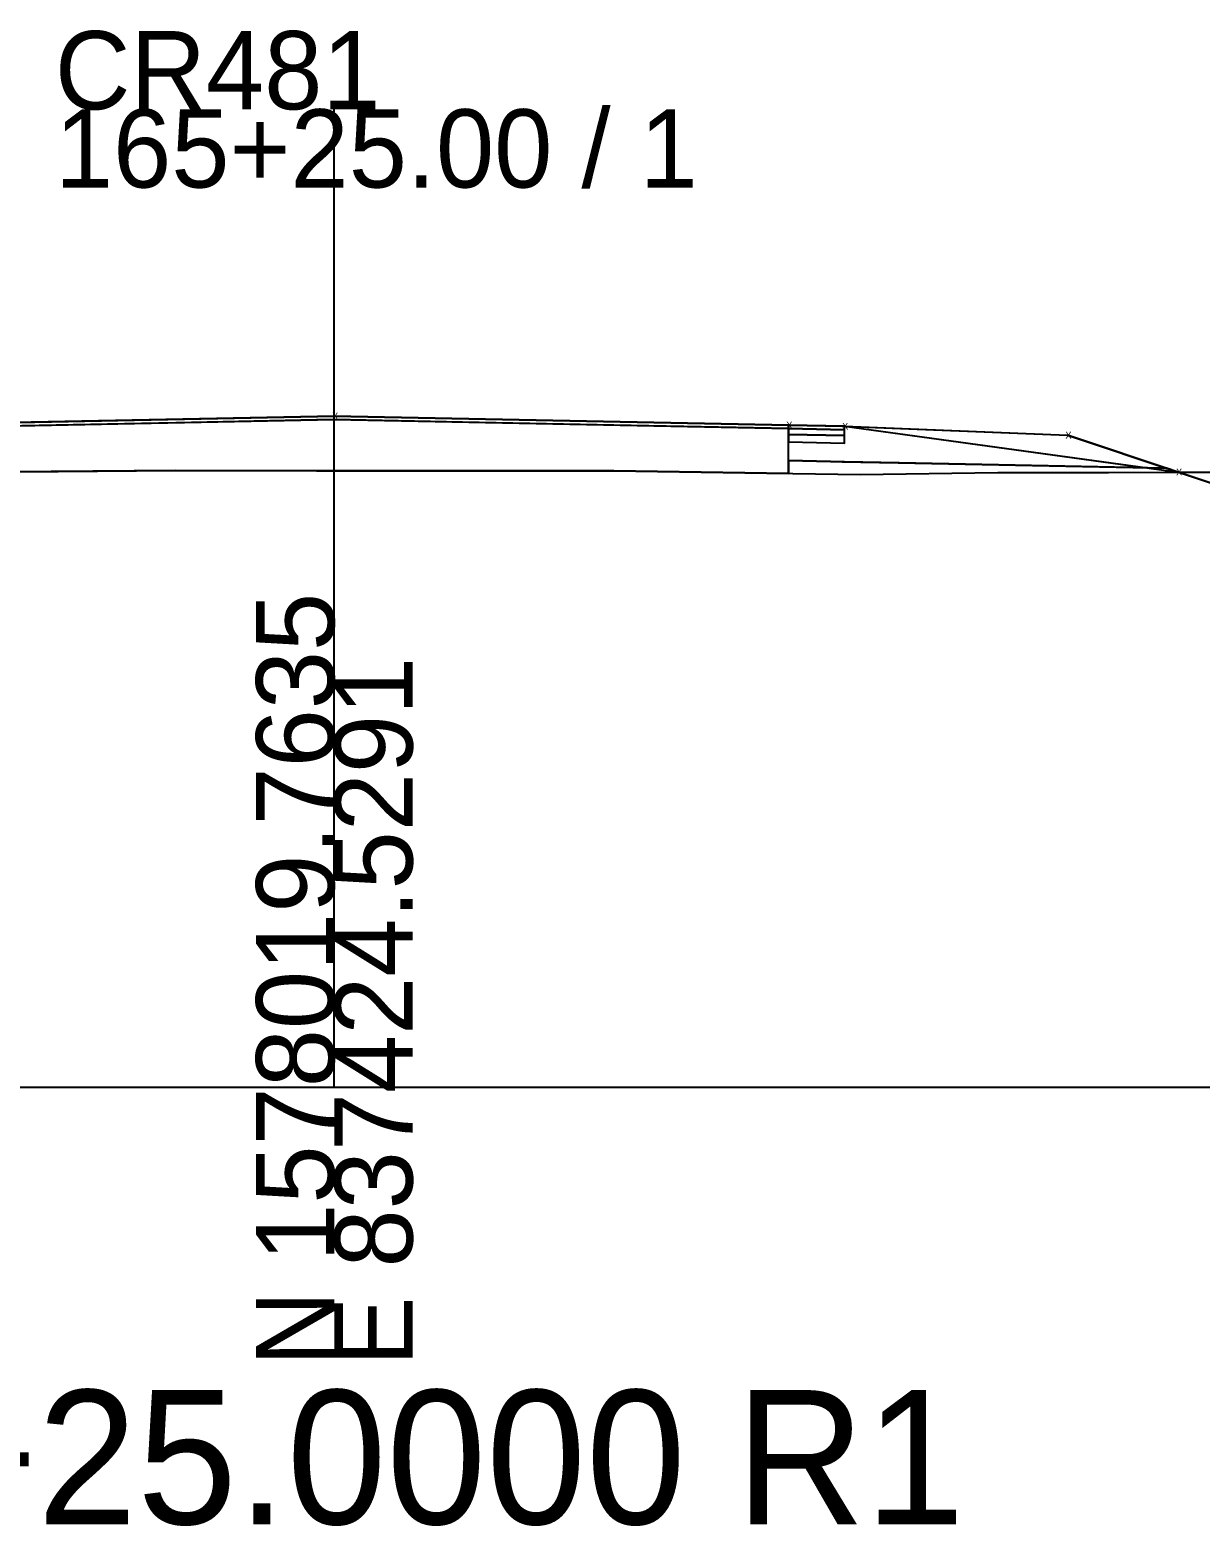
# Model space of a CAD drawing. Extents: x -26 to 303, y -16 to 6048.
# Drawn here: x 139.1 to 181, y 3984.3 to 4037.8 of the extents above; entities that cross this region are included whole.
import ezdxf

# ---------------------------------------------------------------- set-up
doc = ezdxf.new("R2010")
doc.units = 0
for name, color, linetype in [('ASPHALT_19MM1', 7, 'Continuous'), ('ASPHALT_9_5MM1', 7, 'Continuous'), ('CONST_LV3', 7, 'Continuous'), ('Draft_XS_Text', 7, 'Continuous'), ('DTM_P_FINISHED_GRADE2', 7, 'Continuous'), ('DTM_TEMP_DROP', 7, 'Continuous'), ('DTM_X_GROUND', 7, 'Continuous'), ('TRANS_PAVED_SHOULDERS', 7, 'Continuous'), ('X_PROFILES_1', 7, 'Continuous'), ('XS_CELL', 7, 'Continuous'), ('XS_M_SHAPES_EARTHWORK', 7, 'Continuous'), ('XS_P_ASPHALT', 7, 'Continuous'), ('XS_P_GROUND', 7, 'Continuous'), ('XS_P_NULL_POINT', 7, 'Continuous'), ('XS_P_SHOULDER', 7, 'Continuous'), ('XS_P_SUBGRADE_GRANULAR', 7, 'Continuous'), ('XS_P_SUBGRADE_LEVELING', 7, 'Continuous'), ('XS_P_SUBGRADE_MILLING', 7, 'Continuous')]:
    doc.layers.add(name, color=color, linetype=linetype)

msp = doc.modelspace()

# ---------------------------------------------------------------- linework, layer by layer
at = {"layer": 'ASPHALT_19MM1'}
msp.add_lwpolyline([(166.254, 4023.361), (166.254, 4023.091), (168.254, 4023.051), (168.254, 4023.321), (166.254, 4023.361)], dxfattribs=at)
at = {"layer": 'ASPHALT_9_5MM1'}
msp.add_lwpolyline([(166.254, 4023.695), (166.254, 4023.57), (168.254, 4023.53), (168.254, 4023.655), (166.254, 4023.695)], dxfattribs=at)
at = {"layer": 'CONST_LV3'}
for points in [[(150, 4024.02), (131.91, 4023.658)], [(150, 4024.02), (168.173, 4023.656)]]:
    msp.add_lwpolyline(points, dxfattribs=at)
at = {"layer": 'DTM_P_FINISHED_GRADE2'}
msp.add_lwpolyline([(119.938, 4021.957), (119.938, 4021.957), (124.103, 4023.346), (131.91, 4023.658), (133.91, 4023.698), (150, 4024.02), (166.254, 4023.695), (168.254, 4023.655), (176.244, 4023.335), (180.203, 4022.015)], dxfattribs=at)
at = {"layer": 'DTM_X_GROUND'}
for points in [[(133.91, 4023.698), (150, 4024.02), (166.254, 4023.695), (166.254, 4023.695), (168.254, 4023.655), (168.254, 4023.655), (180.203, 4022.015), (180.203, 4022.015), (180.203, 4022.015), (185.132, 4022.015), (190.426, 4022.061), (194.742, 4022.061), (195.877, 4022.065), (200.356, 4022.064), (205.858, 4022.086)], [(95.689, 4022.111), (97.798, 4022.111), (104.708, 4022.08), (107.112, 4022.08), (109.652, 4022.08), (116.732, 4021.989), (120.318, 4021.954), (124.862, 4021.956), (130.296, 4021.955), (144.322, 4022.065), (149.366, 4022.063), (154.591, 4022.06), (160.007, 4022.057), (168.822, 4021.928), (173.744, 4022.002), (177.71, 4022.001), (179.731, 4022.015), (185.132, 4022.015), (190.426, 4022.061), (194.742, 4022.061), (195.877, 4022.065), (200.356, 4022.064), (205.858, 4022.086)]]:
    msp.add_lwpolyline(points, dxfattribs=at)
at = {"layer": 'TRANS_PAVED_SHOULDERS'}
msp.add_lwpolyline([(166.254, 4023.57), (166.254, 4023.361), (168.254, 4023.321), (168.254, 4023.53), (166.254, 4023.57)], dxfattribs=at)
at = {"layer": 'XS_CELL'}
for p, q in [((150, 4000), (150, 4035)), ((0, 4000), (150, 4000)), ((150, 4000), (300, 4000))]:
    msp.add_line(p, q, dxfattribs=at)
at = {"layer": 'XS_M_SHAPES_EARTHWORK'}
for points in [[(121.497, 4022.179), (131.91, 4023.658), (133.91, 4023.698), (150, 4024.02), (166.254, 4023.695), (168.254, 4023.655), (179.098, 4022.167), (170.213, 4022.345), (168.254, 4022.384), (166.254, 4022.424), (166.254, 4021.965), (160.007, 4022.057), (154.591, 4022.06), (150, 4022.062), (149.366, 4022.063), (144.322, 4022.065), (133.91, 4021.984), (133.91, 4022.427), (131.91, 4022.387), (129.91, 4022.347)], [(179.098, 4022.167), (180.195, 4022.016), (179.785, 4022.153)], [(180.195, 4022.016), (180.203, 4022.015), (185.132, 4022.015), (190.426, 4022.061), (194.742, 4022.061), (195.877, 4022.065), (200.356, 4022.064), (201.898, 4022.07), (201.898, 4014.782)]]:
    msp.add_lwpolyline(points, close=True, dxfattribs=at)
at = {"layer": 'XS_P_ASPHALT'}
msp.add_lwpolyline([(133.91, 4023.698), (133.91, 4023.573), (133.91, 4023.573), (150, 4023.895), (166.254, 4023.57), (166.254, 4023.57), (166.254, 4023.695), (166.254, 4023.695), (166.254, 4023.695), (150, 4024.02), (133.91, 4023.698), (133.91, 4023.698), (133.91, 4023.698)], dxfattribs=at)
at = {"layer": 'XS_P_GROUND'}
for points in [[(180.203, 4022.015), (180.203, 4022.015), (176.244, 4023.335)], [(176.244, 4023.333), (201.898, 4014.782)]]:
    msp.add_lwpolyline(points, dxfattribs=at)
at = {"layer": 'XS_P_SHOULDER'}
for points in [[(168.173, 4023.656), (176.244, 4023.333)], [(168.254, 4023.655), (176.244, 4023.335)]]:
    msp.add_lwpolyline(points, dxfattribs=at)
at = {"layer": 'XS_P_SUBGRADE_GRANULAR'}
for points in [[(166.254, 4022.424), (166.254, 4023.695)], [(166.254, 4022.424), (168.254, 4022.384)], [(168.173, 4022.386), (170.173, 4022.346), (179.785, 4022.153)], [(168.173, 4022.386), (170.173, 4022.346), (179.785, 4022.153)], [(168.254, 4022.384), (170.254, 4022.344), (179.79, 4022.153)]]:
    msp.add_lwpolyline(points, dxfattribs=at)
at = {"layer": 'XS_P_SUBGRADE_LEVELING'}
for points in [[(166.254, 4023.57), (160.007, 4023.695), (160.007, 4023.695), (154.591, 4023.803), (154.591, 4023.803), (150, 4023.895), (149.366, 4023.882), (149.366, 4023.882), (144.322, 4023.781), (144.322, 4023.781), (133.91, 4023.573)], [(133.91, 4021.984), (144.322, 4022.065), (144.322, 4022.065), (149.366, 4022.063), (149.366, 4022.063), (150, 4022.062), (154.591, 4022.06), (154.591, 4022.06), (160.007, 4022.057), (160.007, 4022.057), (166.254, 4021.965), (166.254, 4021.965), (166.254, 4023.57), (166.254, 4023.57), (166.254, 4023.57)]]:
    msp.add_lwpolyline(points, dxfattribs=at)
at = {"layer": 'XS_P_SUBGRADE_MILLING'}
msp.add_lwpolyline([(166.254, 4021.965), (166.254, 4021.965), (160.007, 4022.057), (160.007, 4022.057), (154.591, 4022.06), (154.591, 4022.06), (150, 4022.062), (149.366, 4022.063), (149.366, 4022.063), (144.322, 4022.065), (144.322, 4022.065), (133.91, 4021.984), (133.91, 4021.984), (133.91, 4021.984)], dxfattribs=at)
msp.add_lwpolyline([(166.254, 4021.965), (166.254, 4021.965), (160.007, 4022.057), (160.007, 4022.057), (154.591, 4022.06), (154.591, 4022.06), (150, 4022.062), (149.366, 4022.063), (149.366, 4022.063), (144.322, 4022.065), (144.322, 4022.065), (133.91, 4021.984), (133.91, 4021.984), (133.91, 4021.984)], dxfattribs=at)

# ---------------------------------------------------------------- texts
at = {"layer": 'Draft_XS_Text'}
msp.add_text('Sta. 165+25.0000 R1', height=4.8, dxfattribs=at).set_placement((111.716, 3984.35))
at = {"layer": 'DTM_TEMP_DROP'}
msp.add_text('X', height=0.24, dxfattribs=at).set_placement((180.125, 4021.895))
at = {"layer": 'X_PROFILES_1'}
msp.add_text('X', height=0.24, dxfattribs=at).set_placement((176.166, 4023.213))
at = {"layer": 'XS_CELL'}
for s, p in [('CR481', (140, 4035)), ('165+25.00 / 1', (140, 4032.2))]:
    msp.add_text(s, height=2.8, dxfattribs=at).set_placement(p)
for s, p in [('N 1578019.7635', (150, 3990)), ('E 837424.5291', (152.8, 3990))]:
    msp.add_text(s, height=2.8, rotation=90, dxfattribs=at).set_placement(p)
at = {"layer": 'XS_P_GROUND'}
msp.add_text('X', height=0.24, dxfattribs=at).set_placement((176.166, 4023.215))
at = {"layer": 'XS_P_NULL_POINT'}
for p in [(149.922, 4023.9), (166.176, 4023.575), (168.176, 4023.535)]:
    msp.add_text('X', height=0.24, dxfattribs=at).set_placement(p)
at = {"layer": 'XS_P_SUBGRADE_GRANULAR'}
msp.add_text('X', height=0.24, dxfattribs=at).set_placement((180.125, 4021.895))

doc.saveas('drawing.dxf')
